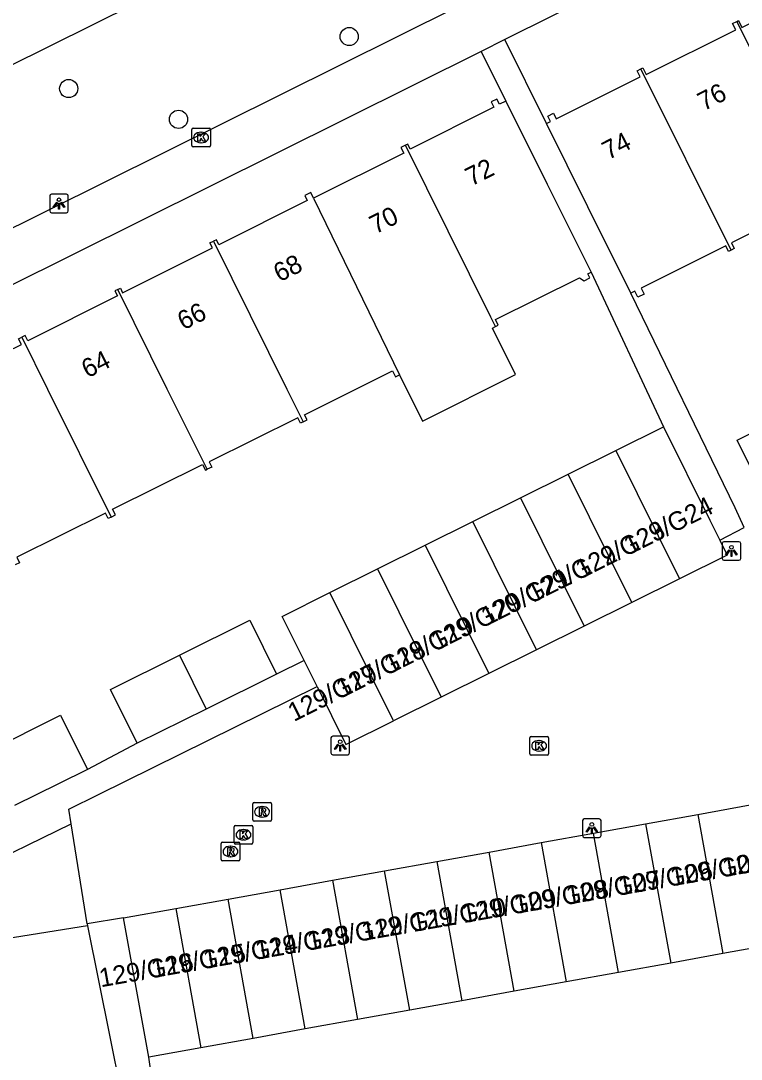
# Model space of a CAD drawing. Extents: x 157793 to 159380, y 380882 to 382313.
# Drawn here: x 158378.2 to 158416.9, y 381464 to 381519.8 of the extents above; entities that cross this region are included whole.
import ezdxf

# ---------------------------------------------------------------- set-up
doc = ezdxf.new("R2010")
doc.units = 0
for name, color, linetype in [('IMGEO_Boom', 7, 'Continuous'), ('IMGEO_Kolk', 7, 'Continuous'), ('IMGEO_Lichtpunt', 7, 'Continuous'), ('IMGEO_Pand', 7, 'Continuous'), ('IMGEO_Pand_nummerreeks', 7, 'Continuous'), ('IMGEO_Rijbaan_lokaal_open', 7, 'Continuous'), ('IMGEO_Rioolput', 7, 'Continuous'), ('IMGEO_Voetpad_open', 7, 'Continuous')]:
    doc.layers.add(name, color=color, linetype=linetype)

msp = doc.modelspace()

# ---------------------------------------------------------------- linework, layer by layer
at = {"layer": 'IMGEO_Boom'}
for centre in [(158395.865, 381518.942), (158380.786, 381516.147), (158386.688, 381514.494)]:
    msp.add_circle(centre, 0.489, dxfattribs=at)
at = {"layer": 'IMGEO_Kolk'}
for p, q in [((158387.402, 381513.091), (158387.402, 381513.943)), ((158387.477, 381514.017), (158388.329, 381514.017)), ((158387.89, 381513.797), (158387.915, 381513.797)), ((158388.403, 381513.943), (158388.403, 381513.091)), ((158388.329, 381513.017), (158387.477, 381513.017)), ((158387.913, 381513.237), (158387.888, 381513.237)), ((158405.573, 381480.405), (158405.573, 381481.257)), ((158405.648, 381481.331), (158406.5, 381481.331)), ((158406.574, 381481.257), (158406.574, 381480.405)), ((158406.061, 381481.111), (158406.086, 381481.111)), ((158406.5, 381480.331), (158405.648, 381480.331)), ((158406.084, 381480.551), (158406.059, 381480.551)), ((158389.68, 381475.629), (158389.68, 381476.481)), ((158389.755, 381476.555), (158390.607, 381476.555)), ((158390.168, 381476.335), (158390.193, 381476.335)), ((158390.681, 381476.481), (158390.681, 381475.629)), ((158390.191, 381475.775), (158390.166, 381475.775)), ((158390.607, 381475.555), (158389.755, 381475.555))]:
    msp.add_line(p, q, dxfattribs=at)
for points in [[(158387.402, 381513.091), (158387.402, 381513.943)], [(158387.477, 381514.017), (158388.329, 381514.017)], [(158387.723, 381513.717), (158387.846, 381513.717), (158387.846, 381513.566), (158387.976, 381513.717), (158388.14, 381513.717), (158387.994, 381513.566), (158388.147, 381513.317), (158387.995, 381513.317), (158387.91, 381513.481), (158387.846, 381513.414), (158387.846, 381513.317), (158387.723, 381513.317), (158387.723, 381513.717)], [(158388.403, 381513.943), (158388.403, 381513.091)], [(158388.329, 381513.017), (158387.477, 381513.017)], [(158405.573, 381480.405), (158405.573, 381481.257)], [(158405.648, 381481.331), (158406.5, 381481.331)], [(158406.574, 381481.257), (158406.574, 381480.405)], [(158405.894, 381481.031), (158406.017, 381481.031), (158406.017, 381480.88), (158406.147, 381481.031), (158406.311, 381481.031), (158406.165, 381480.88), (158406.318, 381480.631), (158406.166, 381480.631), (158406.081, 381480.795), (158406.017, 381480.728), (158406.017, 381480.631), (158405.894, 381480.631), (158405.894, 381481.031)], [(158406.5, 381480.331), (158405.648, 381480.331)], [(158389.68, 381475.629), (158389.68, 381476.481)], [(158389.755, 381476.555), (158390.607, 381476.555)], [(158390.001, 381476.255), (158390.124, 381476.255), (158390.124, 381476.104), (158390.254, 381476.255), (158390.418, 381476.255), (158390.272, 381476.104), (158390.425, 381475.855), (158390.273, 381475.855), (158390.188, 381476.019), (158390.124, 381475.952), (158390.124, 381475.855), (158390.001, 381475.855), (158390.001, 381476.255)], [(158390.681, 381476.481), (158390.681, 381475.629)], [(158390.607, 381475.555), (158389.755, 381475.555)]]:
    msp.add_lwpolyline(points, dxfattribs=at)
for centre, start, end in [((158387.479, 381513.941), 91.552, 178.448), ((158387.479, 381513.941), 91.552, 178.448), ((158388.327, 381513.941), 1.552, 88.448), ((158388.327, 381513.941), 1.552, 88.448), ((158387.479, 381513.093), 181.552, 268.448), ((158387.479, 381513.093), 181.552, 268.448), ((158388.327, 381513.093), 271.552, 358.448), ((158388.327, 381513.093), 271.552, 358.448), ((158405.65, 381481.255), 91.552, 178.448), ((158405.65, 381481.255), 91.552, 178.448), ((158406.498, 381481.255), 1.552, 88.448), ((158406.498, 381481.255), 1.552, 88.448), ((158405.65, 381480.407), 181.552, 268.448), ((158405.65, 381480.407), 181.552, 268.448), ((158406.498, 381480.407), 271.552, 358.448), ((158406.498, 381480.407), 271.552, 358.448), ((158389.757, 381476.479), 91.552, 178.448), ((158389.757, 381476.479), 91.552, 178.448), ((158390.605, 381476.479), 1.552, 88.448), ((158390.605, 381476.479), 1.552, 88.448), ((158389.757, 381475.631), 181.552, 268.448), ((158389.757, 381475.631), 181.552, 268.448), ((158390.605, 381475.631), 271.552, 358.448), ((158390.605, 381475.631), 271.552, 358.448)]:
    msp.add_arc(centre, 0.0765, start, end, dxfattribs=at)
for centre, major_axis, ratio, start_param, end_param in [((158387.889, 381513.517), (-0.387, 0.002), 0.722429, 4.712389, 7.853982), ((158387.914, 381513.517), (-0.39, 0.002), 0.717154, 1.570796, 4.712389), ((158406.06, 381480.831), (-0.387, 0.002), 0.722429, 4.712389, 7.853982), ((158406.085, 381480.831), (-0.39, 0.002), 0.717154, 1.570796, 4.712389), ((158390.167, 381476.055), (-0.387, 0.002), 0.722429, 4.712389, 7.853982), ((158390.192, 381476.055), (-0.39, 0.002), 0.717154, 1.570796, 4.712389)]:
    msp.add_ellipse(centre, major_axis=major_axis, ratio=ratio, start_param=start_param, end_param=end_param, dxfattribs=at)
at = {"layer": 'IMGEO_Lichtpunt'}
for p, q in [((158379.764, 381510.378), (158379.764, 381509.571)), ((158379.764, 381510.378), (158379.764, 381509.571)), ((158380.666, 381510.473), (158379.858, 381510.473)), ((158380.666, 381510.473), (158379.858, 381510.473)), ((158380.76, 381509.571), (158380.76, 381510.378)), ((158380.76, 381509.571), (158380.76, 381510.378)), ((158379.858, 381509.477), (158380.666, 381509.477)), ((158379.858, 381509.477), (158380.666, 381509.477)), ((158416.816, 381491.801), (158416.008, 381491.801)), ((158416.816, 381491.801), (158416.008, 381491.801)), ((158415.914, 381491.706), (158415.914, 381490.899)), ((158415.914, 381491.706), (158415.914, 381490.899)), ((158416.91, 381490.899), (158416.91, 381491.706)), ((158416.91, 381490.899), (158416.91, 381491.706)), ((158416.008, 381490.805), (158416.816, 381490.805)), ((158416.008, 381490.805), (158416.816, 381490.805)), ((158394.881, 381481.255), (158394.881, 381480.448)), ((158394.881, 381481.255), (158394.881, 381480.448)), ((158395.783, 381481.35), (158394.975, 381481.35)), ((158395.783, 381481.35), (158394.975, 381481.35)), ((158395.877, 381480.448), (158395.877, 381481.255)), ((158395.877, 381480.448), (158395.877, 381481.255)), ((158394.975, 381480.354), (158395.783, 381480.354)), ((158394.975, 381480.354), (158395.783, 381480.354)), ((158408.408, 381476.813), (158408.408, 381476.006)), ((158408.408, 381476.813), (158408.408, 381476.006)), ((158409.31, 381476.908), (158408.502, 381476.908)), ((158409.31, 381476.908), (158408.502, 381476.908)), ((158409.404, 381476.006), (158409.404, 381476.813)), ((158409.404, 381476.006), (158409.404, 381476.813)), ((158408.502, 381475.912), (158409.31, 381475.912)), ((158408.502, 381475.912), (158409.31, 381475.912))]:
    msp.add_line(p, q, dxfattribs=at)
for points in [[(158380.138, 381510.042), (158380.177, 381510.014), (158379.989, 381509.752), (158379.951, 381509.779), (158380.138, 381510.042)], [(158380.24, 381509.994), (158380.287, 381509.994), (158380.287, 381509.672), (158380.24, 381509.672), (158380.24, 381509.994)], [(158380.35, 381510.014), (158380.388, 381510.041), (158380.575, 381509.779), (158380.536, 381509.751), (158380.35, 381510.014)], [(158416.288, 381491.37), (158416.327, 381491.342), (158416.139, 381491.08), (158416.101, 381491.107), (158416.288, 381491.37)], [(158416.39, 381491.322), (158416.437, 381491.322), (158416.437, 381491), (158416.39, 381491), (158416.39, 381491.322)], [(158416.5, 381491.342), (158416.538, 381491.369), (158416.725, 381491.107), (158416.686, 381491.079), (158416.5, 381491.342)], [(158395.255, 381480.919), (158395.294, 381480.891), (158395.106, 381480.629), (158395.068, 381480.656), (158395.255, 381480.919)], [(158395.357, 381480.871), (158395.404, 381480.871), (158395.404, 381480.549), (158395.357, 381480.549), (158395.357, 381480.871)], [(158395.467, 381480.891), (158395.505, 381480.918), (158395.692, 381480.656), (158395.653, 381480.628), (158395.467, 381480.891)], [(158408.782, 381476.477), (158408.821, 381476.449), (158408.633, 381476.187), (158408.595, 381476.214), (158408.782, 381476.477)], [(158408.884, 381476.429), (158408.931, 381476.429), (158408.931, 381476.107), (158408.884, 381476.107), (158408.884, 381476.429)], [(158408.994, 381476.449), (158409.032, 381476.476), (158409.219, 381476.214), (158409.18, 381476.186), (158408.994, 381476.449)]]:
    msp.add_lwpolyline(points, dxfattribs=at)
for centre in [(158380.263, 381510.176), (158416.413, 381491.504), (158395.38, 381481.053), (158408.907, 381476.611)]:
    msp.add_circle(centre, 0.0994, dxfattribs=at)
for centre, start, end in [((158379.858, 381510.378), 90, 180), ((158379.858, 381510.378), 90, 180), ((158380.666, 381510.378), 0, 90), ((158380.666, 381510.378), 0, 90), ((158379.858, 381509.571), 180, 270), ((158379.858, 381509.571), 180, 270), ((158380.666, 381509.571), 270, 0), ((158380.666, 381509.571), 270, 360), ((158416.008, 381491.706), 90, 180), ((158416.008, 381491.706), 90, 180), ((158416.816, 381491.706), 0, 90), ((158416.816, 381491.706), 0, 90), ((158416.008, 381490.899), 180, 270), ((158416.008, 381490.899), 180, 270), ((158416.816, 381490.899), 270, 0), ((158416.816, 381490.899), 270, 360), ((158394.975, 381481.255), 90, 180), ((158394.975, 381481.255), 90, 180), ((158395.783, 381481.255), 0, 90), ((158395.783, 381481.255), 0, 90), ((158394.975, 381480.448), 180, 270), ((158394.975, 381480.448), 180, 270), ((158395.783, 381480.448), 270, 0), ((158395.783, 381480.448), 270, 360), ((158408.502, 381476.813), 90, 180), ((158408.502, 381476.813), 90, 180), ((158409.31, 381476.813), 0, 90), ((158409.31, 381476.813), 0, 90), ((158408.502, 381476.006), 180, 270), ((158408.502, 381476.006), 180, 270), ((158409.31, 381476.006), 270, 0), ((158409.31, 381476.006), 270, 360)]:
    msp.add_arc(centre, 0.0946, start, end, dxfattribs=at)
at = {"layer": 'IMGEO_Pand'}
for points in [[(158416.695, 381519.749), (158416.791, 381519.797), (158416.978, 381519.423), (158421.751, 381521.799), (158421.569, 381522.164), (158421.839, 381522.298)], [(158411.547, 381517.208), (158411.654, 381517.261), (158411.831, 381516.905), (158416.642, 381519.3), (158416.473, 381519.638), (158416.695, 381519.749)], [(158416.695, 381519.749), (158421.532, 381510.032)], [(158406.467, 381514.271), (158406.682, 381514.378), (158406.535, 381514.672), (158406.838, 381514.823), (158406.984, 381514.529), (158411.498, 381516.776), (158411.336, 381517.103), (158411.547, 381517.208)], [(158416.394, 381507.47), (158411.547, 381517.208)], [(158404.28, 381515.478), (158403.936, 381515.306), (158403.798, 381515.583), (158403.497, 381515.433), (158403.642, 381515.145), (158399.143, 381512.897), (158399.011, 381513.161), (158398.891, 381513.101)], [(158404.28, 381515.478), (158406.515, 381511.006), (158408.872, 381506.289)], [(158411.008, 381505.149), (158408.695, 381509.795), (158406.467, 381514.271)], [(158398.891, 381513.101), (158398.647, 381512.979), (158398.794, 381512.684), (158393.943, 381510.26)], [(158403.723, 381503.359), (158403.474, 381503.861), (158398.891, 381513.101)], [(158393.943, 381510.26), (158393.796, 381510.561), (158393.477, 381510.402), (158393.612, 381510.133), (158388.855, 381507.756), (158388.722, 381508.022), (158388.576, 381507.949)], [(158393.943, 381510.26), (158398.571, 381500.771)], [(158421.532, 381510.032), (158421.358, 381509.945), (158421.211, 381510.241), (158416.419, 381507.855), (158416.567, 381507.556), (158416.394, 381507.47)], [(158383.426, 381505.359), (158383.56, 381505.426), (158383.684, 381505.176), (158388.509, 381507.587), (158388.378, 381507.85), (158388.576, 381507.949)], [(158388.576, 381507.949), (158392.518, 381500), (158393.39, 381498.243)], [(158416.394, 381507.47), (158416.249, 381507.398), (158416.104, 381507.69), (158411.559, 381505.427), (158411.719, 381505.105), (158411.383, 381504.937), (158411.224, 381505.257), (158411.008, 381505.149)], [(158403.723, 381503.359), (158403.88, 381503.438), (158403.733, 381503.732), (158408.238, 381505.983), (158408.487, 381505.819), (158408.804, 381505.977), (158408.692, 381506.199), (158408.872, 381506.289)], [(158383.426, 381505.359), (158383.27, 381505.281), (158383.406, 381505.008), (158378.586, 381502.6), (158378.443, 381502.885), (158378.262, 381502.795)], [(158388.223, 381495.688), (158386.084, 381500), (158383.426, 381505.359)], [(158398.571, 381500.771), (158399.805, 381498.282), (158404.806, 381500.781), (158403.566, 381503.281), (158403.723, 381503.359)], [(158373.088, 381500.249), (158373.213, 381500.304), (158373.324, 381500), (158378.239, 381502.397), (158378.085, 381502.706), (158378.262, 381502.795)], [(158378.262, 381502.795), (158379.648, 381500), (158383.062, 381493.117)], [(158393.39, 381498.243), (158393.597, 381498.346), (158393.461, 381498.62), (158396.218, 381500), (158398.188, 381500.986), (158398.351, 381500.661), (158398.571, 381500.771)], [(158421.967, 381496.274), (158418.147, 381494.373), (158416.713, 381497.254), (158420.533, 381499.154)], [(158393.39, 381498.243), (158393.242, 381498.17), (158393.098, 381498.46), (158388.336, 381496.094), (158388.475, 381495.813), (158388.223, 381495.688)], [(158410.196, 381496.698), (158412.758, 381497.971)], [(158412.758, 381497.971), (158415.246, 381492.963), (158415.78, 381491.888)], [(158407.634, 381495.425), (158410.196, 381496.698)], [(158410.196, 381496.698), (158413.62, 381489.806)], [(158383.062, 381493.117), (158383.299, 381493.235), (158383.145, 381493.544), (158387.984, 381495.948), (158388.135, 381495.644), (158388.223, 381495.688)], [(158405.072, 381494.152), (158407.634, 381495.425)], [(158411.058, 381488.533), (158407.634, 381495.425)], [(158402.51, 381492.879), (158405.072, 381494.152)], [(158405.072, 381494.152), (158408.496, 381487.26)], [(158383.062, 381493.117), (158382.908, 381493.041), (158382.76, 381493.339), (158377.988, 381490.968), (158378.138, 381490.667), (158377.9, 381490.549)], [(158399.948, 381491.607), (158402.51, 381492.879)], [(158405.934, 381485.988), (158402.51, 381492.879)], [(158415.78, 381491.888), (158416.182, 381491.079), (158413.62, 381489.806)], [(158397.387, 381490.334), (158399.948, 381491.607)], [(158399.948, 381491.607), (158403.373, 381484.715)], [(158394.825, 381489.061), (158397.387, 381490.334)], [(158397.387, 381490.334), (158400.811, 381483.442)], [(158413.62, 381489.806), (158411.058, 381488.533)], [(158393.438, 381485.424), (158393.386, 381485.528), (158392.263, 381487.788), (158394.825, 381489.061)], [(158398.249, 381482.169), (158394.825, 381489.061)], [(158411.058, 381488.533), (158408.496, 381487.26)], [(158386.741, 381485.699), (158390.521, 381487.577), (158391.956, 381484.688)], [(158408.496, 381487.26), (158405.934, 381485.988)], [(158384.469, 381480.968), (158383.033, 381483.857), (158386.741, 381485.699)], [(158386.741, 381485.699), (158388.175, 381482.809)], [(158405.934, 381485.988), (158403.373, 381484.715)], [(158394.133, 381484.024), (158393.438, 381485.424)], [(158391.956, 381484.688), (158388.175, 381482.809)], [(158403.373, 381484.715), (158400.811, 381483.442)], [(158394.133, 381484.024), (158395.687, 381480.896), (158398.249, 381482.169)], [(158400.811, 381483.442), (158398.249, 381482.169)], [(158376.433, 381480.531), (158380.345, 381482.475), (158381.789, 381479.568)], [(158388.175, 381482.809), (158384.469, 381480.968)], [(158381.789, 381479.568), (158380.233, 381478.795), (158377.876, 381477.623)], [(158414.605, 381477.15), (158417.412, 381477.656)], [(158411.799, 381476.644), (158414.605, 381477.15)], [(158414.605, 381477.15), (158415.955, 381469.665)], [(158375.466, 381473.993), (158380.914, 381476.648)], [(158381.772, 381471.271), (158380.914, 381476.648)], [(158408.993, 381476.138), (158411.799, 381476.644)], [(158411.799, 381476.644), (158413.149, 381469.159)], [(158403.38, 381475.126), (158406.186, 381475.632)], [(158406.186, 381475.632), (158408.993, 381476.138)], [(158406.186, 381475.632), (158407.536, 381468.147)], [(158410.342, 381468.653), (158408.993, 381476.138)], [(158400.574, 381474.62), (158403.38, 381475.126)], [(158404.73, 381467.641), (158403.38, 381475.126)], [(158397.768, 381474.114), (158400.574, 381474.62)], [(158400.574, 381474.62), (158401.923, 381467.135)], [(158381.791, 381471.153), (158376.065, 381470.239), (158375.466, 381473.993)], [(158394.961, 381473.608), (158397.768, 381474.114)], [(158399.117, 381466.629), (158397.768, 381474.114)], [(158392.155, 381473.102), (158394.961, 381473.608)], [(158394.961, 381473.608), (158396.311, 381466.123)], [(158389.349, 381472.596), (158392.155, 381473.102)], [(158393.505, 381465.617), (158392.155, 381473.102)], [(158386.542, 381472.09), (158389.349, 381472.596)], [(158390.698, 381465.111), (158389.349, 381472.596)], [(158383.736, 381471.584), (158386.542, 381472.09)], [(158386.542, 381472.09), (158387.892, 381464.605)], [(158381.772, 381471.271), (158381.791, 381471.153)], [(158385.085, 381464.099), (158384.623, 381466.664), (158383.736, 381471.584)], [(158418.761, 381470.171), (158415.955, 381469.665)], [(158415.955, 381469.665), (158413.149, 381469.159)], [(158413.149, 381469.159), (158410.342, 381468.653)], [(158410.342, 381468.653), (158407.536, 381468.147)], [(158407.536, 381468.147), (158404.73, 381467.641)], [(158404.73, 381467.641), (158401.923, 381467.135)], [(158401.923, 381467.135), (158399.117, 381466.629)], [(158399.117, 381466.629), (158396.311, 381466.123)], [(158393.505, 381465.617), (158390.698, 381465.111)], [(158396.311, 381466.123), (158393.505, 381465.617)], [(158390.698, 381465.111), (158387.892, 381464.605)], [(158387.892, 381464.605), (158385.085, 381464.099)]]:
    msp.add_lwpolyline(points, dxfattribs=at)
at = {"layer": 'IMGEO_Rijbaan_lokaal_open'}
for points in [[(158415.78, 381491.888), (158417.1, 381492.563)], [(158380.914, 381476.648), (158380.79, 381477.425), (158382.384, 381478.213), (158394.133, 381484.024)], [(158383.736, 381471.584), (158381.772, 381471.271)]]:
    msp.add_lwpolyline(points, dxfattribs=at)
at = {"layer": 'IMGEO_Rioolput'}
for p, q in [((158390.681, 381476.86), (158390.681, 381477.712)), ((158390.756, 381477.786), (158391.608, 381477.786)), ((158391.169, 381477.566), (158391.194, 381477.566)), ((158391.682, 381477.712), (158391.682, 381476.86)), ((158391.608, 381476.786), (158390.756, 381476.786)), ((158391.192, 381477.006), (158391.167, 381477.006)), ((158389.056, 381475.654), (158389.908, 381475.654)), ((158388.981, 381474.728), (158388.981, 381475.58)), ((158389.469, 381475.434), (158389.494, 381475.434)), ((158389.982, 381475.58), (158389.982, 381474.728)), ((158389.908, 381474.654), (158389.056, 381474.654)), ((158389.492, 381474.874), (158389.467, 381474.874))]:
    msp.add_line(p, q, dxfattribs=at)
for points in [[(158390.681, 381476.86), (158390.681, 381477.712)], [(158390.756, 381477.786), (158391.608, 381477.786)], [(158391.27, 381477.484), (158391.018, 381477.486), (158391.018, 381477.086)], [(158391.196, 381477.405), (158391.142, 381477.405), (158391.142, 381477.324)], [(158391.142, 381477.324), (158391.194, 381477.324)], [(158391.682, 381477.712), (158391.682, 381476.86)], [(158391.608, 381476.786), (158390.756, 381476.786)], [(158391.018, 381477.086), (158391.142, 381477.086), (158391.142, 381477.248), (158391.153, 381477.248)], [(158391.2, 381477.219), (158391.271, 381477.086), (158391.411, 381477.086), (158391.346, 381477.212)], [(158389.056, 381475.654), (158389.908, 381475.654)], [(158388.981, 381474.728), (158388.981, 381475.58)], [(158389.57, 381475.352), (158389.318, 381475.354), (158389.318, 381474.954)], [(158389.318, 381474.954), (158389.442, 381474.954), (158389.442, 381475.116), (158389.453, 381475.116)], [(158389.496, 381475.273), (158389.442, 381475.273), (158389.442, 381475.192)], [(158389.442, 381475.192), (158389.494, 381475.192)], [(158389.5, 381475.087), (158389.571, 381474.954), (158389.711, 381474.954), (158389.646, 381475.08)], [(158389.982, 381475.58), (158389.982, 381474.728)], [(158389.908, 381474.654), (158389.056, 381474.654)]]:
    msp.add_lwpolyline(points, dxfattribs=at)
for centre, radius, start, end in [((158390.758, 381477.71), 0.0765, 91.552, 178.448), ((158390.758, 381477.71), 0.0765, 91.552, 178.448), ((158391.178, 381477.513), 0.19, 274.7715, 282.9687), ((158391.202, 381477.309), 0.0964, 77.0061, 93.1865), ((158391.216, 381477.366), 0.0378, 276.6634, 79.6772), ((158391.269, 381477.374), 0.109, 350.3612, 89.416), ((158391.267, 381477.374), 0.112, 277.5842, 350.9817), ((158391.606, 381477.71), 0.0765, 1.552, 88.448), ((158391.606, 381477.71), 0.0765, 1.552, 88.448), ((158390.758, 381476.862), 0.0765, 181.552, 268.448), ((158390.758, 381476.862), 0.0765, 181.552, 268.448), ((158391.152, 381477.195), 0.0533, 26.0293, 88.6989), ((158391.251, 381477.159), 0.108, 29.5134, 73.7905), ((158391.606, 381476.862), 0.0765, 271.552, 358.448), ((158391.606, 381476.862), 0.0765, 271.552, 358.448), ((158389.058, 381475.578), 0.0765, 91.552, 178.448), ((158389.058, 381475.578), 0.0765, 91.552, 178.448), ((158389.906, 381475.578), 0.0765, 1.552, 88.448), ((158389.906, 381475.578), 0.0765, 1.552, 88.448), ((158389.452, 381475.063), 0.0533, 26.0293, 88.6989), ((158389.478, 381475.381), 0.19, 274.7715, 282.9687), ((158389.502, 381475.177), 0.0964, 77.0061, 93.1865), ((158389.516, 381475.234), 0.0378, 276.6634, 79.6772), ((158389.569, 381475.242), 0.109, 350.3612, 89.416), ((158389.567, 381475.242), 0.112, 277.5842, 350.9817), ((158389.551, 381475.027), 0.108, 29.5134, 73.7905), ((158389.058, 381474.73), 0.0765, 181.552, 268.448), ((158389.058, 381474.73), 0.0765, 181.552, 268.448), ((158389.906, 381474.73), 0.0765, 271.552, 358.448), ((158389.906, 381474.73), 0.0765, 271.552, 358.448)]:
    msp.add_arc(centre, radius, start, end, dxfattribs=at)
for centre, major_axis, ratio, start_param, end_param in [((158391.168, 381477.286), (-0.387, 0.002), 0.722429, 4.712389, 7.853982), ((158391.193, 381477.286), (-0.39, 0.002), 0.717154, 1.570796, 4.712389), ((158389.468, 381475.154), (-0.387, 0.002), 0.722429, 4.712389, 7.853982), ((158389.493, 381475.154), (-0.39, 0.002), 0.717154, 1.570796, 4.712389)]:
    msp.add_ellipse(centre, major_axis=major_axis, ratio=ratio, start_param=start_param, end_param=end_param, dxfattribs=at)
at = {"layer": 'IMGEO_Voetpad_open'}
for points in [[(158429.862, 381531.521), (158404.227, 381518.778)], [(158401.658, 381520.527), (158398.164, 381527.551), (158372.857, 381515.012), (158376.436, 381508.005)], [(158401.658, 381520.527), (158376.436, 381508.005)], [(158404.227, 381518.778), (158402.954, 381518.145)], [(158406.467, 381514.271), (158404.227, 381518.778)], [(158402.954, 381518.145), (158366.45, 381500), (158351.122, 381492.381)], [(158402.954, 381518.145), (158404.28, 381515.478)], [(158408.872, 381506.289), (158412.758, 381497.971)], [(158417.1, 381492.563), (158416.609, 381493.625), (158411.008, 381505.149)], [(158393.438, 381485.424), (158391.956, 381484.688)], [(158384.469, 381480.968), (158381.789, 381479.568)], [(158381.791, 381471.153), (158384.783, 381456.299)], [(158386.078, 381457.157), (158385.085, 381464.099)]]:
    msp.add_lwpolyline(points, dxfattribs=at)

# ---------------------------------------------------------------- texts
at = {"layer": 'IMGEO_Pand_nummerreeks'}
for s, rotation, p in [('76', 27.1638, (158414.922, 381514.924)), ('74', 27.1638, (158409.793, 381512.292)), ('72', 26.5623, (158402.425, 381510.883)), ('70', 26.5623, (158397.272, 381508.307)), ('68', 26.5623, (158392.113, 381505.727)), ('66', 26.5651, (158386.95, 381503.146)), ('64', 26.5623, (158381.791, 381500.567)), ('129/G24', 26.4498, (158410.945, 381491.092)), ('129/G23', 26.4498, (158408.354, 381489.803)), ('129/G22', 26.4498, (158405.757, 381488.511)), ('129/G21', 26.4498, (158403.27, 381487.274)), ('129/G20', 26.4498, (158400.583, 381485.938)), ('129/G19', 26.4498, (158398.068, 381484.686)), ('129/G18', 26.4498, (158395.483, 381483.4)), ('129/G17', 26.4477, (158392.888, 381482.11)), ('129/G04', 10.0232, (158416.018, 381473.778)), ('129/G05', 10.0232, (158413.219, 381473.283)), ('129/G06', 10.0232, (158410.419, 381472.788)), ('129/G07', 10.0232, (158407.62, 381472.294)), ('129/G08', 10.0232, (158404.823, 381471.799)), ('129/G09', 10.0232, (158402.018, 381471.303)), ('129/G10', 10.0232, (158399.314, 381470.826)), ('129/G11', 10.0232, (158396.62, 381470.35)), ('129/G13', 10.0232, (158390.913, 381469.341)), ('129/G12', 10.0232, (158393.706, 381469.834)), ('129/G14', 10.0232, (158388.113, 381468.846)), ('129/G15', 10.0232, (158385.314, 381468.351)), ('129/G16', 10.0232, (158382.514, 381467.856))]:
    msp.add_text(s, height=1, rotation=rotation, dxfattribs=at).set_placement(p)

doc.saveas('drawing.dxf')
